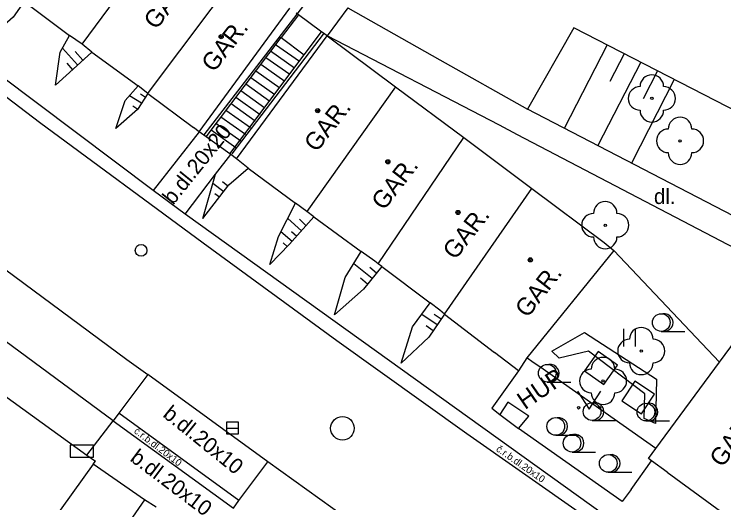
# Model space of a CAD drawing. Extents: x -595546 to -593986, y -1160845 to -1159202.
# Drawn here: x -595079.64 to -595049.5, y -1160694.97 to -1160674.23 of the extents above; entities that cross this region are included whole.
import ezdxf

# ---------------------------------------------------------------- set-up
doc = ezdxf.new("R2010")
doc.units = 0
for name, color, linetype in [('Level 22', 7, 'Continuous'), ('Level 24', 7, 'Continuous'), ('Level 26', 7, 'Continuous'), ('Level 27', 7, 'Continuous'), ('Level 28', 7, 'Continuous'), ('Level 36', 7, 'Continuous'), ('Level 39', 7, 'Continuous'), ('plynovod - povrch.  znaky - PRIS skut. velikost', 7, 'Continuous'), ('TM - budovy zdene_ betonove - VP', 7, 'Continuous'), ('TM - chodniky - VP', 7, 'Continuous'), ('TM - dolni hrana svahu', 7, 'Continuous'), ('TM - horni hrana svahu', 7, 'Continuous'), ('TM - komunikace - VP', 7, 'Continuous'), ('TM - letecke snimky - pomocna linie', 7, 'Continuous'), ('TM - plot drateny_ kovovy - VP', 7, 'Continuous'), ('TM - podezdivka plotu - VP', 7, 'Continuous'), ('TM - pomocna konstrukcni linie', 7, 'Continuous'), ('TM - popis objektu', 7, 'Continuous'), ('TM - popis povrchu', 7, 'Continuous'), ('TM - rozhrani mezi zpev. plochami mezi sebou - VP', 7, 'Continuous'), ('TM - rozhrani ploch obecne - VP', 7, 'Continuous'), ('TM - schody - VP', 7, 'Continuous'), ('TM - srafovani', 7, 'Continuous'), ('TM - vjezd na pozemek', 7, 'Continuous'), ('TM - vstup do budovy - zdene_ betonove', 7, 'Continuous'), ('TM - zabradli - VP', 7, 'Continuous')]:
    doc.layers.add(name, color=color, linetype=linetype)

msp = doc.modelspace()

# ---------------------------------------------------------------- linework, layer by layer
at = {"layer": 'Level 22'}
for centre in [(-595052.56, -1160677.81), (-595051.36, -1160679.61), (-595054.54, -1160683.19), (-595053.01, -1160688.53), (-595054.63, -1160689.8)]:
    msp.add_circle(centre, 0.05, dxfattribs=at)
for centre, start, end in [((-595052.56, -1160677.31), 0, 180), ((-595053.06, -1160677.81), 90, 270), ((-595052.06, -1160677.81), 270, 90), ((-595052.56, -1160678.31), 180, 0), ((-595051.36, -1160679.11), 0, 180), ((-595051.86, -1160679.61), 90, 270), ((-595050.86, -1160679.61), 270, 90), ((-595051.36, -1160680.11), 180, 0), ((-595054.54, -1160682.69), 0, 180), ((-595055.04, -1160683.19), 90, 270), ((-595054.04, -1160683.19), 270, 90), ((-595054.54, -1160683.69), 180, 0), ((-595053.01, -1160688.03), 0, 180), ((-595053.51, -1160688.53), 90, 270), ((-595052.51, -1160688.53), 270, 90), ((-595054.63, -1160689.3), 0, 180), ((-595053.01, -1160689.03), 180, 0), ((-595055.13, -1160689.8), 90, 270), ((-595054.13, -1160689.8), 270, 90), ((-595054.63, -1160690.3), 180, 0)]:
    msp.add_arc(centre, 0.5, start, end, dxfattribs=at)
at = {"layer": 'Level 24'}
msp.add_lwpolyline([(-595077.268, -1160693.029), (-595076.268, -1160693.029), (-595076.268, -1160692.529), (-595077.268, -1160692.529)], close=True, dxfattribs=at)
at = {"layer": 'Level 26'}
for points in [[(-595055.417, -1160689.366), (-595054.604, -1160689.948), (-595054.022, -1160689.134), (-595054.836, -1160688.552)], [(-595053.833, -1160690.639), (-595053.001, -1160691.193), (-595052.447, -1160690.361), (-595053.279, -1160689.807)]]:
    msp.add_lwpolyline(points, close=True, dxfattribs=at)
at = {"layer": 'Level 27'}
msp.add_line((-595070.62, -1160691.8), (-595070.12, -1160691.8), dxfattribs=at)
msp.add_lwpolyline([(-595070.62, -1160692.05), (-595070.12, -1160692.05), (-595070.12, -1160691.55), (-595070.62, -1160691.55)], close=True, dxfattribs=at)
msp.add_circle((-595065.7, -1160691.81), 0.5, dxfattribs=at)
at = {"layer": 'Level 28'}
msp.add_circle((-595074.25, -1160684.26), 0.25, dxfattribs=at)
at = {"layer": 'Level 36'}
for p, q in [((-595053.754, -1160688.343), (-595053.754, -1160687.593)), ((-595053.254, -1160688.343), (-595053.254, -1160687.593)), ((-595052.16, -1160687.695), (-595051.16, -1160687.695)), ((-595057, -1160689.845), (-595056, -1160689.845)), ((-595055.1, -1160691.475), (-595054.1, -1160691.475)), ((-595052.81, -1160691.495), (-595051.81, -1160691.495)), ((-595056.64, -1160692.105), (-595055.64, -1160692.105)), ((-595055.95, -1160692.815), (-595054.95, -1160692.815)), ((-595054.41, -1160693.675), (-595053.41, -1160693.675))]:
    msp.add_line(p, q, dxfattribs=at)
msp.add_lwpolyline([(-595055.72, -1160690.24), (-595055.22, -1160690.99), (-595054.72, -1160690.24)], dxfattribs=at)
for centre, radius in [((-595052.16, -1160687.32), 0.375), ((-595057, -1160689.47), 0.375), ((-595055.1, -1160691.1), 0.375), ((-595055.67, -1160690.94), 0.05), ((-595054.771, -1160690.94), 0.05), ((-595052.81, -1160691.12), 0.375), ((-595056.64, -1160691.73), 0.375), ((-595055.95, -1160692.44), 0.375), ((-595054.41, -1160693.3), 0.375)]:
    msp.add_circle(centre, radius, dxfattribs=at)
for centre in [(-595052.035, -1160687.32), (-595056.875, -1160689.47), (-595054.975, -1160691.1), (-595052.685, -1160691.12), (-595056.515, -1160691.73), (-595055.825, -1160692.44), (-595054.285, -1160693.3)]:
    msp.add_arc(centre, 0.375, 260.4059, 99.5941, dxfattribs=at)
at = {"layer": 'Level 39'}
for centre, radius in [((-595070.85, -1160675.19), 0.09), ((-595070.85, -1160675.19), 0.0398), ((-595066.75, -1160678.33), 0.09), ((-595066.75, -1160678.33), 0.0398), ((-595063.77, -1160680.5), 0.09), ((-595063.77, -1160680.5), 0.0398), ((-595060.79, -1160682.65), 0.09), ((-595060.79, -1160682.65), 0.0398), ((-595057.72, -1160684.66), 0.09), ((-595057.72, -1160684.66), 0.0398)]:
    msp.add_circle(centre, radius, dxfattribs=at)
at = {"layer": 'plynovod - povrch.  znaky - PRIS skut. velikost'}
for points in [[(-595058.67, -1160690.7), (-595059.01, -1160691.22)], [(-595057.79, -1160691.3), (-595058.67, -1160690.7)], [(-595059.01, -1160691.22), (-595058.22, -1160691.82)], [(-595058.22, -1160691.82), (-595057.79, -1160691.3)]]:
    msp.add_lwpolyline(points, dxfattribs=at)
at = {"layer": 'TM - budovy zdene_ betonove - VP'}
for points in [[(-595076.76, -1160675.5), (-595072.83, -1160670.2)], [(-595073.97, -1160677.6), (-595073.89, -1160677.5), (-595069.99, -1160672.3)], [(-595071.79, -1160679.23), (-595067.94, -1160673.98)], [(-595076.76, -1160675.5), (-595077.29, -1160675.14)], [(-595070.2, -1160680.37), (-595066.35, -1160675.16)], [(-595066.35, -1160675.16), (-595063.45, -1160677.32)], [(-595076.34, -1160675.85), (-595076.76, -1160675.5)], [(-595073.97, -1160677.6), (-595074.38, -1160677.27)], [(-595063.45, -1160677.32), (-595067.21, -1160682.61)], [(-595063.45, -1160677.32), (-595060.55, -1160679.47)], [(-595071.79, -1160679.23), (-595072.02, -1160679.04)], [(-595064.18, -1160684.83), (-595060.55, -1160679.47)], [(-595060.55, -1160679.47), (-595057.65, -1160681.63)], [(-595069.7, -1160680.77), (-595070.2, -1160680.37)], [(-595061.36, -1160686.96), (-595057.65, -1160681.63)], [(-595057.65, -1160681.63), (-595054.58, -1160683.92)], [(-595067.21, -1160682.61), (-595067.69, -1160682.25)], [(-595066.91, -1160682.84), (-595067.21, -1160682.61)], [(-595054.58, -1160683.92), (-595054.17, -1160684.27)], [(-595064.33, -1160684.71), (-595064.9, -1160684.31)], [(-595054.17, -1160684.27), (-595057.87, -1160688.82)], [(-595064.18, -1160684.83), (-595064.33, -1160684.71)], [(-595064.03, -1160684.94), (-595064.18, -1160684.83)], [(-595061.56, -1160686.8), (-595061.97, -1160686.49)], [(-595061.36, -1160686.96), (-595061.56, -1160686.8)], [(-595049.68, -1160689), (-595048.72, -1160687.7), (-595045.89, -1160689.66)], [(-595058.22, -1160689.37), (-595059.24, -1160688.59)], [(-595057.87, -1160688.82), (-595058.22, -1160689.37)], [(-595082, -1160689.01), (-595076.55, -1160692.95)], [(-595052.39, -1160692.67), (-595049.68, -1160689)], [(-595052.7, -1160693.09), (-595052.39, -1160692.67)], [(-595076.55, -1160692.95), (-595076.19, -1160693.21)], [(-595052.57, -1160693.19), (-595052.7, -1160693.09)], [(-595076.28, -1160693.33), (-595078.95, -1160697.04)], [(-595076.28, -1160693.33), (-595076.19, -1160693.21)], [(-595051.91, -1160693.67), (-595052.57, -1160693.19)]]:
    msp.add_lwpolyline(points, dxfattribs=at)
at = {"layer": 'TM - chodniky - VP'}
for points in [[(-595043.02, -1160685.94), (-595057.84, -1160678.27)], [(-595042.3, -1160687.68), (-595058.26, -1160679.35)], [(-595075.44, -1160691.49), (-595086.16, -1160683.59), (-595084.65, -1160681.6)], [(-595058.22, -1160689.37), (-595059.36, -1160690.96)], [(-595073.96, -1160689.53), (-595075.19, -1160691.17)], [(-595059.36, -1160690.96), (-595059.01, -1160691.22)], [(-595075.19, -1160691.17), (-595075.44, -1160691.49)], [(-595053.82, -1160694.92), (-595058.22, -1160691.82)], [(-595070.1, -1160694.87), (-595068.87, -1160693.23)], [(-595053.44, -1160694.4), (-595052.57, -1160693.19)], [(-595053.44, -1160694.4), (-595053.82, -1160694.92)], [(-595070.33, -1160695.2), (-595070.1, -1160694.87)]]:
    msp.add_lwpolyline(points, dxfattribs=at)
at = {"layer": 'TM - dolni hrana svahu'}
for points in [[(-595077.88, -1160677.24), (-595077.69, -1160675.84), (-595077.29, -1160675.14)], [(-595075.32, -1160679.09), (-595074.93, -1160677.9), (-595074.38, -1160677.27)], [(-595071.63, -1160682.91), (-595071.09, -1160681.02)], [(-595068.78, -1160684.86), (-595068.42, -1160683.67), (-595067.69, -1160682.25)], [(-595066.03, -1160687), (-595065.59, -1160685.41), (-595064.9, -1160684.31)], [(-595063.2, -1160689.05), (-595062.73, -1160687.5), (-595061.97, -1160686.49)]]:
    msp.add_lwpolyline(points, dxfattribs=at)
at = {"layer": 'TM - horni hrana svahu'}
for points in [[(-595079.22, -1160673.7), (-595079.68, -1160674.36), (-595080.53, -1160675.09)], [(-595044.83, -1160680.49), (-595055.87, -1160674.81)], [(-595077.88, -1160677.24), (-595076.98, -1160676.42), (-595076.34, -1160675.85)], [(-595073.97, -1160677.6), (-595074.41, -1160678.28), (-595075.32, -1160679.09)], [(-595071.63, -1160682.91), (-595070.52, -1160681.47), (-595069.7, -1160680.77)], [(-595066.91, -1160682.84), (-595067.95, -1160683.99), (-595068.78, -1160684.86)], [(-595064.03, -1160684.94), (-595064.81, -1160685.9), (-595066.03, -1160687)], [(-595061.36, -1160686.96), (-595062.03, -1160687.94), (-595063.2, -1160689.05)]]:
    msp.add_lwpolyline(points, dxfattribs=at)
at = {"layer": 'TM - komunikace - VP'}
for points in [[(-595078.56, -1160678.83), (-595087.77, -1160671.81)], [(-595071.62, -1160683.95), (-595078.56, -1160678.83)], [(-595082.04, -1160683.58), (-595074.85, -1160688.89)], [(-595065.94, -1160688.09), (-595071.62, -1160683.95)], [(-595060.42, -1160692.04), (-595065.94, -1160688.09)], [(-595074.85, -1160688.89), (-595073.96, -1160689.53)], [(-595068.87, -1160693.23), (-595073.96, -1160689.53)], [(-595050.54, -1160698.96), (-595060.42, -1160692.04)], [(-595062.79, -1160697.59), (-595068.87, -1160693.23)]]:
    msp.add_lwpolyline(points, dxfattribs=at)
at = {"layer": 'TM - letecke snimky - pomocna linie'}
for points in [[(-595065.47, -1160673.97), (-595061.57, -1160676.17)], [(-595059.03, -1160678.95), (-595066.35, -1160675.16)], [(-595061.57, -1160676.17), (-595057.84, -1160678.27)], [(-595058.26, -1160679.35), (-595059.03, -1160678.95)]]:
    msp.add_lwpolyline(points, dxfattribs=at)
at = {"layer": 'TM - plot drateny_ kovovy - VP'}
msp.add_lwpolyline([(-595074.1, -1160694.85), (-595083.26, -1160708.04)], dxfattribs=at)
at = {"layer": 'TM - podezdivka plotu - VP'}
for points in [[(-595067.57, -1160674.26), (-595068.3, -1160675.22)], [(-595067.57, -1160674.26), (-595067.66, -1160674.19)], [(-595067.32, -1160675.96), (-595066.59, -1160674.98)], [(-595066.35, -1160675.16), (-595066.59, -1160674.98)], [(-595071.49, -1160679.44), (-595068.3, -1160675.22)], [(-595070.48, -1160680.16), (-595067.32, -1160675.96)], [(-595071.49, -1160679.44), (-595071.79, -1160679.23)], [(-595070.44, -1160680.19), (-595070.48, -1160680.16)], [(-595073.61, -1160695.16), (-595074.1, -1160694.85)]]:
    msp.add_lwpolyline(points, dxfattribs=at)
at = {"layer": 'TM - pomocna konstrukcni linie'}
msp.add_lwpolyline([(-595055.87, -1160674.81), (-595057.84, -1160678.27)], dxfattribs=at)
at = {"layer": 'TM - rozhrani mezi zpev. plochami mezi sebou - VP'}
for points in [[(-595073.74, -1160681.72), (-595083.58, -1160674.33)], [(-595071.79, -1160679.23), (-595073.74, -1160681.72)], [(-595071.09, -1160681.02), (-595070.44, -1160680.19)], [(-595070.2, -1160680.37), (-595070.44, -1160680.19)], [(-595072.38, -1160682.72), (-595071.09, -1160681.02)], [(-595072.38, -1160682.72), (-595073.74, -1160681.72)], [(-595054.57, -1160695.49), (-595072.38, -1160682.72)], [(-595070.1, -1160694.87), (-595075.19, -1160691.17)], [(-595076.55, -1160692.95), (-595075.44, -1160691.49)], [(-595075.44, -1160691.49), (-595070.33, -1160695.2)]]:
    msp.add_lwpolyline(points, dxfattribs=at)
at = {"layer": 'TM - rozhrani ploch obecne - VP'}
for points in [[(-595065.47, -1160673.97), (-595066.35, -1160675.16)], [(-595066.63, -1160674.95), (-595067.57, -1160674.26)], [(-595066.59, -1160674.98), (-595066.63, -1160674.95)], [(-595068.3, -1160675.22), (-595067.32, -1160675.96)], [(-595070.48, -1160680.16), (-595071.49, -1160679.44)], [(-595049.68, -1160689), (-595054.17, -1160684.27)], [(-595056.8, -1160688.53), (-595055.42, -1160687.74), (-595052.36, -1160689.72), (-595052.4, -1160691.61), (-595052.89, -1160691.39), (-595052.86, -1160690.35), (-595055.25, -1160688.53), (-595056.49, -1160688.83), (-595056.8, -1160688.53)], [(-595057.6, -1160689.01), (-595057.87, -1160688.82)], [(-595057.32, -1160689.2), (-595057.6, -1160689.01)], [(-595052.39, -1160692.67), (-595057.32, -1160689.2)]]:
    msp.add_lwpolyline(points, dxfattribs=at)
at = {"layer": 'TM - schody - VP'}
for points in [[(-595067.53, -1160676.24), (-595068.54, -1160675.53)], [(-595067.74, -1160676.52), (-595068.75, -1160675.81)], [(-595067.94, -1160676.8), (-595068.96, -1160676.09)], [(-595068.15, -1160677.09), (-595069.17, -1160676.37)], [(-595068.36, -1160677.37), (-595069.38, -1160676.65)], [(-595068.57, -1160677.65), (-595069.59, -1160676.93)], [(-595068.78, -1160677.94), (-595069.8, -1160677.21)], [(-595069.19, -1160678.5), (-595070.23, -1160677.77)], [(-595068.99, -1160678.22), (-595070.01, -1160677.49)], [(-595069.4, -1160678.78), (-595070.43, -1160678.04)], [(-595069.61, -1160679.06), (-595070.65, -1160678.32)], [(-595069.82, -1160679.34), (-595070.86, -1160678.6)], [(-595070.02, -1160679.63), (-595071.07, -1160678.88)], [(-595070.23, -1160679.91), (-595071.28, -1160679.16)]]:
    msp.add_lwpolyline(points, dxfattribs=at)
at = {"layer": 'TM - srafovani'}
for points in [[(-595054.45, -1160675.54), (-595056.28, -1160679.08)], [(-595077.59, -1160675.67), (-595076.95, -1160676.39)], [(-595077.05, -1160675.82), (-595076.72, -1160676.19)], [(-595053.74, -1160675.91), (-595054.35, -1160677.09)], [(-595077.41, -1160676.32), (-595077.17, -1160676.59)], [(-595053.03, -1160676.27), (-595054.86, -1160679.81)], [(-595052.32, -1160676.64), (-595052.93, -1160677.82)], [(-595051.61, -1160677), (-595053.43, -1160680.55)], [(-595074.74, -1160677.68), (-595074.23, -1160678)], [(-595074.27, -1160677.62), (-595074.07, -1160677.75)], [(-595074.6, -1160678.12), (-595074.39, -1160678.26)], [(-595070.79, -1160681.34), (-595070.56, -1160681.52)], [(-595071.2, -1160681.4), (-595070.74, -1160681.76)], [(-595071.12, -1160681.84), (-595070.92, -1160681.99)], [(-595068.02, -1160682.9), (-595067.44, -1160683.43)], [(-595067.53, -1160682.94), (-595067.24, -1160683.21)], [(-595068.31, -1160683.45), (-595067.84, -1160683.87)], [(-595067.87, -1160683.45), (-595067.64, -1160683.65)], [(-595068.22, -1160683.94), (-595068.05, -1160684.1)], [(-595065.22, -1160684.82), (-595064.44, -1160685.44)], [(-595064.54, -1160684.97), (-595064.25, -1160685.21)], [(-595064.93, -1160685.43), (-595064.63, -1160685.68)], [(-595062.33, -1160686.96), (-595061.67, -1160687.41)], [(-595061.8, -1160686.96), (-595061.5, -1160687.17)], [(-595062.14, -1160687.45), (-595061.84, -1160687.66)]]:
    msp.add_lwpolyline(points, dxfattribs=at)
at = {"layer": 'TM - vjezd na pozemek'}
msp.add_lwpolyline([(-595074.1, -1160694.85), (-595076.28, -1160693.33)], dxfattribs=at)
at = {"layer": 'TM - vstup do budovy - zdene_ betonove'}
for points in [[(-595079.22, -1160673.7), (-595077.29, -1160675.14)], [(-595076.34, -1160675.85), (-595074.38, -1160677.27)], [(-595073.97, -1160677.6), (-595072.02, -1160679.04)], [(-595069.7, -1160680.77), (-595067.69, -1160682.25)], [(-595066.91, -1160682.84), (-595064.9, -1160684.31)], [(-595064.03, -1160684.94), (-595061.97, -1160686.49)], [(-595061.36, -1160686.96), (-595059.24, -1160688.59)], [(-595051.91, -1160693.67), (-595049.65, -1160695.32)]]:
    msp.add_lwpolyline(points, dxfattribs=at)
at = {"layer": 'TM - zabradli - VP'}
for points in [[(-595071.57, -1160679.36), (-595067.1, -1160673.54)], [(-595066.47, -1160675.03), (-595070.39, -1160680.16)]]:
    msp.add_lwpolyline(points, dxfattribs=at)

# ---------------------------------------------------------------- texts
at = {"layer": 'TM - popis objektu'}
for s, rotation, p in [('GAR.', 52.15, (-595073.61, -1160674.93)), ('GAR.', 52.15, (-595071.16, -1160676.74)), ('GAR.', 52.15, (-595066.8, -1160680.13)), ('GAR.', 52.15, (-595063.94, -1160682.6)), ('GAR.', 52.15, (-595060.91, -1160684.7)), ('GAR.', 52.15, (-595057.84, -1160687.16)), ('HUP', 34.5402, (-595057.95, -1160691.04)), ('GAR.', 54.1513, (-595049.56, -1160693.51))]:
    msp.add_text(s, height=0.75, rotation=rotation, dxfattribs=at).set_placement(p)
at = {"layer": 'TM - popis povrchu'}
for s, height, rotation, p in [('b.dl.20x20', 0.65, 51.1501, (-595072.89, -1160682.36)), ('b.dl.20x10', 0.65, 321.1457, (-595073.37, -1160691.29)), ('č.r.b.dl.20x10', 0.3, 322.5939, (-595074.58, -1160691.98)), ('č.r.b.dl.20x10', 0.3, 324.9365, (-595059.2, -1160692.75)), ('b.dl.20x10', 0.65, 323, (-595074.76, -1160693.16))]:
    msp.add_text(s, height=height, rotation=rotation, dxfattribs=at).set_placement(p)
msp.add_text('dl.', height=0.65, dxfattribs=at).set_placement((-595052.47, -1160682.29))

doc.saveas('drawing.dxf')
